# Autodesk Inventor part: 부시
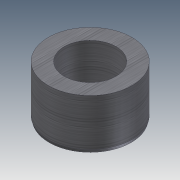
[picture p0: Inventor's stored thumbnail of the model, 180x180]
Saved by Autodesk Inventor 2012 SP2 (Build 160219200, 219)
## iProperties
Company: 한국ATC센터
Created: 2014-11
Part Number: 부시
Document SubType Name: Modeling
Designer: KYOUNG IL JANG
Density: 7.86 g/cm^3
Material: 강, 연강
Mass: 167.601 g
Surface Area: 70.0223 cm^2
Volume: 21.3233 cm^3
Author: KYOUNG IL JANG
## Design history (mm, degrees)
sketch "스케치1"
  geometry: C1 r 21 at (0, 0); C2 r 13 at (0, 0); 1 further point
  constraints: 2 centre point, 2 coincident
  dimensions: "d4" = 26 diameter of C2; "d5" = 42 diameter of C1
extrude "돌출1" new body sketch "스케치1" distance "d0" = 25; taper "d1" = 0 deg
chamfer "모따기1" distance "d6" = 1.5; stored, may be unused: second distance "d7" = 2, angle "d8" = 15 deg
node "솔리드1"
